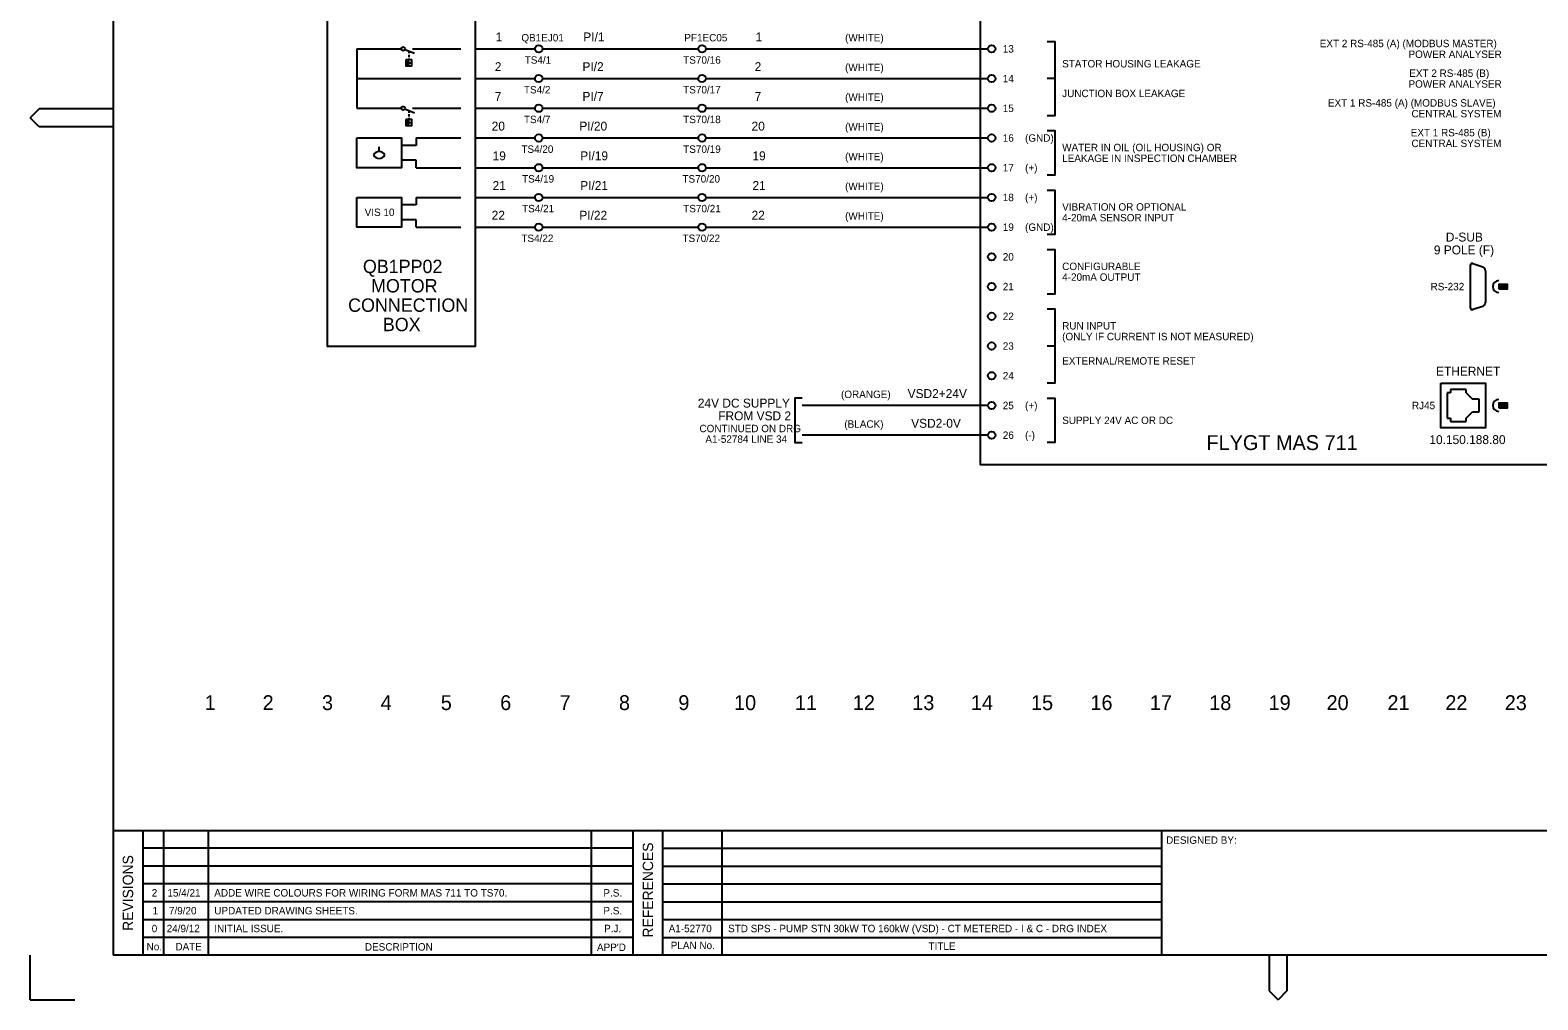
# Model space of a CAD drawing. Extents: x 0 to 841, y 0 to 594.
# Drawn here: x 0 to 508, y 0 to 326 of the extents above; entities that cross this region are included whole.
import ezdxf

# ---------------------------------------------------------------- set-up
doc = ezdxf.new("R2010")
doc.units = 0
for name, color, linetype in [('A1BORDER', 7, 'Continuous'), ('Level 1', 7, 'Continuous'), ('Level 10', 7, 'Continuous'), ('Level 5', 7, 'Continuous'), ('Level 6', 7, 'Continuous')]:
    doc.layers.add(name, color=color, linetype=linetype)

msp = doc.modelspace()

# ---------------------------------------------------------------- linework, layer by layer
at = {"layer": 'A1BORDER'}
for p, q in [((28, 581), (28, 15)), ((3, 299.76), (0, 296.76)), ((28, 299.76), (3, 299.76)), ((3, 293.76), (0, 296.76)), ((28, 293.76), (3, 293.76)), ((28, 57), (829, 57)), ((38, 15), (38, 57)), ((45, 15), (45, 57)), ((60, 15), (60, 57)), ((189, 15), (189, 57)), ((203, 15), (203, 57)), ((213, 15), (213, 57)), ((233, 15), (233, 57)), ((381, 15), (381, 57)), ((203, 51), (38, 51)), ((213, 51), (381, 51)), ((203, 45), (38, 45)), ((213, 45), (381, 45)), ((203, 39), (38, 39)), ((213, 39), (381, 39)), ((203, 33), (38, 33)), ((213, 33), (381, 33)), ((38, 27), (203, 27)), ((213, 27), (381, 27)), ((203, 21), (38, 21)), ((213, 21), (381, 21)), ((0, 0), (0, 15)), ((829, 15), (28, 15)), ((417.19, 15), (417.19, 3)), ((423.19, 15), (423.19, 3)), ((0, 0), (15, 0)), ((417.19, 3), (420.19, 0)), ((423.19, 3), (420.19, 0))]:
    msp.add_line(p, q, dxfattribs=at)
at = {"layer": 'Level 1'}
for p, q in [((110, 320), (125, 320)), ((110, 320), (110, 300)), ((128.75, 320), (130, 320)), ((130, 320), (145, 320)), ((227.5, 320), (322.5, 320)), ((126.2, 319.77), (129.38, 318.5)), ((127.5, 319.25), (127.5, 318.5)), ((127.5, 318), (127.5, 317.25)), ((127.5, 316.75), (127.5, 316.25)), ((127.64, 315.25), (128.15, 315.25)), ((110, 310), (145, 310)), ((227.5, 310), (322.5, 310)), ((345, 310), (342.5, 310)), ((110, 300), (125, 300)), ((126.2, 299.77), (129.38, 298.5)), ((128.75, 300), (130, 300)), ((130, 300), (145, 300)), ((227.5, 300), (322.5, 300)), ((127.5, 299.25), (127.5, 298.5)), ((127.5, 298), (127.5, 297.25)), ((127.5, 296.75), (127.5, 296.25)), ((127.64, 295.25), (128.15, 295.25)), ((130, 290), (145, 290)), ((130, 290), (130, 287.5)), ((227.5, 290), (322.5, 290)), ((130, 287.5), (125, 287.5)), ((130, 282.5), (125, 282.5)), ((130, 280), (130, 282.5)), ((130, 280), (145, 280)), ((227.5, 280), (322.5, 280)), ((130, 270), (145, 270)), ((130, 270), (130, 267.5)), ((227.5, 270), (322.5, 270)), ((130, 267.5), (125, 267.5)), ((130, 262.5), (125, 262.5)), ((130, 260), (130, 262.5)), ((130, 260), (145, 260)), ((227.5, 260), (322.5, 260)), ((485, 232.69), (485, 247.32)), ((485.72, 247.76), (489.17, 246.68)), ((490, 245.34), (490, 234.68)), ((494.5, 240.5), (497.5, 240.5)), ((494.5, 240.25), (497.5, 240.25)), ((494.5, 240), (497.5, 240)), ((494.5, 239.75), (497.5, 239.75)), ((494.5, 239.5), (497.5, 239.5)), ((489.17, 233.34), (485.72, 232.25)), ((345, 220), (342.5, 220)), ((477.14, 204.29), (477.14, 195.71)), ((478.21, 204.29), (477.14, 204.29)), ((483.57, 205.36), (478.21, 205.36)), ((478.21, 205.36), (478.21, 204.29)), ((483.57, 204.29), (483.57, 205.36)), ((483.57, 204.29), (485.71, 202.14)), ((322.5, 200), (260, 200)), ((487.86, 202.14), (485.71, 202.14)), ((487.86, 197.86), (487.86, 202.14)), ((494.5, 200.5), (497.5, 200.5)), ((494.5, 200.25), (497.5, 200.25)), ((494.5, 200), (497.5, 200)), ((494.5, 199.75), (497.5, 199.75)), ((494.5, 199.5), (497.5, 199.5)), ((477.14, 195.71), (478.21, 195.71)), ((478.21, 195.71), (478.21, 194.64)), ((478.21, 194.64), (483.57, 194.64)), ((483.57, 195.71), (485.71, 197.86)), ((483.57, 194.64), (483.57, 195.71)), ((485.71, 197.86), (487.86, 197.86)), ((322.5, 190), (260, 190))]:
    msp.add_line(p, q, dxfattribs=at)
for points in [[(150, 500), (100, 500), (100, 220), (150, 220)], [(320, 450), (520, 450), (520, 180), (320, 180)], [(126.5, 316.25), (126.5, 314.25), (128.5, 314.25), (128.5, 316.25)], [(126.5, 296.25), (126.5, 294.25), (128.5, 294.25), (128.5, 296.25)], [(110, 290), (125, 290), (125, 280), (110, 280)], [(110, 270), (125, 270), (125, 260), (110, 260)], [(475, 207.5), (490, 207.5), (490, 192.5), (475, 192.5)]]:
    msp.add_lwpolyline(points, close=True, dxfattribs=at)
for points in [[(342.5, 322.5), (345, 322.5), (345, 297.5), (342.5, 297.5)], [(342.5, 292.5), (345, 292.5), (345, 277.5), (342.5, 277.5)], [(342.5, 272.5), (345, 272.5), (345, 257.5), (342.5, 257.5)], [(342.5, 252.5), (345, 252.5), (345, 237.5), (342.5, 237.5)], [(342.5, 232.5), (345, 232.5), (345, 207.5), (342.5, 207.5)], [(260, 202.5), (257.5, 202.5), (257.5, 187.5), (260, 187.5)], [(342.5, 202.5), (345, 202.5), (345, 187.5), (342.5, 187.5)]]:
    msp.add_lwpolyline(points, dxfattribs=at)
for centre in [(125.63, 320), (125.63, 300)]:
    msp.add_circle(centre, 0.625, dxfattribs=at)
for centre, radius, start, end in [((127.56, 315.26), 0.699, 116.5651, 243.4349), ((126.93, 315.26), 0.699, 296.5651, 63.4349), ((127.56, 295.26), 0.699, 116.5651, 243.4349), ((126.93, 295.26), 0.699, 296.5651, 63.4349), ((485.5, 247.32), 0.5, 63.6594, 179.5468), ((488.5, 245.33), 1.5, 0.2965, 63.6295), ((488.5, 234.69), 1.5, 296.4323, 359.7035), ((485.5, 232.69), 0.5, 180.4532, 296.4699)]:
    msp.add_arc(centre, radius, start, end, dxfattribs=at)
at = {"layer": 'Level 10'}
msp.add_line((117.5, 285.45), (117.5, 287), dxfattribs=at)
for points in [[(494.5, 239.25), (497.5, 239.25), (497.5, 240.75), (494.5, 240.75)], [(494.5, 199.25), (497.5, 199.25), (497.5, 200.75), (494.5, 200.75)]]:
    msp.add_lwpolyline(points, close=True, dxfattribs=at)
for centre, radius, start, end in [((117.5, 283.36), 2.1, 26.5651, 153.435), ((117.5, 285.24), 2.1, 206.5651, 333.4349), ((494.5, 240), 2, 90, 270), ((494.5, 200), 2, 90, 270)]:
    msp.add_arc(centre, radius, start, end, dxfattribs=at)
at = {"layer": 'Level 5'}
for centre in [(171.25, 320), (226.25, 320), (323.75, 320), (171.25, 310), (226.25, 310), (323.75, 310), (171.25, 300), (226.25, 300), (323.75, 300), (171.25, 290), (226.25, 290), (323.75, 290), (171.25, 280), (226.25, 280), (323.75, 280), (171.25, 270), (226.25, 270), (323.75, 270), (171.25, 260), (226.25, 260), (323.75, 260), (323.75, 250), (323.75, 240), (323.75, 230), (323.75, 220), (323.75, 210), (323.75, 200), (323.75, 190)]:
    msp.add_circle(centre, 1.25, dxfattribs=at)
at = {"layer": 'Level 6'}
for p, q in [((150, 320), (170, 320)), ((172.5, 320), (225, 320)), ((150, 310), (170, 310)), ((172.5, 310), (225, 310)), ((150, 300), (170, 300)), ((172.5, 300), (225, 300)), ((150, 290), (170, 290)), ((172.5, 290), (225, 290)), ((150, 280), (170, 280)), ((172.5, 280), (225, 280)), ((150, 270), (170, 270)), ((172.5, 270), (225, 270)), ((150, 260), (170, 260)), ((172.5, 260), (225, 260))]:
    msp.add_line(p, q, dxfattribs=at)

# ---------------------------------------------------------------- texts
at = {"layer": 'A1BORDER'}
for s, p in [('REFERENCES', (209.76, 20.96)), ('REVISIONS', (34.68, 23.2))]:
    msp.add_text(s, height=3.5, rotation=90, dxfattribs=at).set_placement(p)
for s, p in [('DESIGNED BY:', (382.5, 52.5)), ('No.', (39.21, 16.65)), ('DATE', (48.92, 16.65)), ('DESCRIPTION', (112.71, 16.57)), ("APP'D", (190.85, 16.44)), ('PLAN No.', (215.69, 17.06)), ('TITLE', (302.5, 16.81))]:
    msp.add_text(s, height=2.5, dxfattribs=at).set_placement(p)
at = {"layer": 'Level 1'}
for s, height, p in [('QB1EJ01', 2.5, (165.4, 322.5)), ('PF1EC05', 2.5, (220.27, 322.5)), ('13', 2.5, (327.5, 318.75)), ('EXT 2 RS-485 (A) (MODBUS MASTER)', 2.5, (434.23, 320.56)), ('TS4/1', 2.5, (166.52, 315)), ('TS70/16', 2.5, (219.9, 315)), ('STATOR HOUSING LEAKAGE', 2.5, (347.5, 313.75)), ('POWER ANALYSER', 2.5, (464.11, 316.94)), ('14', 2.5, (327.5, 308.75)), ('EXT 2 RS-485 (B)', 2.5, (464.36, 310.56)), ('TS4/2', 2.5, (166.27, 305)), ('TS70/17', 2.5, (219.9, 305)), ('JUNCTION BOX LEAKAGE', 2.5, (347.5, 303.75)), ('POWER ANALYSER', 2.5, (464.11, 306.94)), ('15', 2.5, (327.5, 298.75)), ('EXT 1 RS-485 (A) (MODBUS SLAVE)', 2.5, (436.97, 300.56)), ('TS4/7', 2.5, (166.27, 295)), ('TS70/18', 2.5, (219.9, 295)), ('CENTRAL SYSTEM', 2.5, (465.11, 296.94)), ('16', 2.5, (327.5, 288.75)), ('(GND)', 2.5, (335, 288.75)), ('EXT 1 RS-485 (B)', 2.5, (464.86, 290.56)), ('CENTRAL SYSTEM', 2.5, (465.11, 286.94)), ('TS4/20', 2.5, (165.4, 285)), ('TS70/19', 2.5, (219.9, 285)), ('WATER IN OIL (OIL HOUSING) OR', 2.5, (347.5, 285.56)), ('LEAKAGE IN INSPECTION CHAMBER', 2.5, (347.5, 281.94)), ('17', 2.5, (327.5, 278.75)), ('(+)', 2.5, (335, 278.75)), ('TS4/19', 2.5, (165.65, 275)), ('TS70/20', 2.5, (219.65, 275)), ('18', 2.5, (327.5, 268.75)), ('(+)', 2.5, (335, 268.75)), ('VIS 10', 2.5, (112.64, 263.75)), ('TS4/21', 2.5, (165.65, 265)), ('TS70/21', 2.5, (219.9, 265)), ('VIBRATION OR OPTIONAL', 2.5, (347.5, 265.56)), ('4-20mA SENSOR INPUT', 2.5, (347.5, 261.94)), ('19', 2.5, (327.5, 258.75)), ('(GND)', 2.5, (335, 258.75)), ('TS4/22', 2.5, (165.4, 255)), ('TS70/22', 2.5, (219.65, 255)), ('20', 2.5, (327.5, 248.75)), ('4-20mA OUTPUT', 2.5, (347.5, 241.94)), ('CONFIGURABLE', 2.5, (347.5, 245.56)), ('21', 2.5, (327.5, 238.75)), ('RS-232', 2.5, (471.54, 238.75)), ('22', 2.5, (327.5, 228.75)), ('(ONLY IF CURRENT IS NOT MEASURED)', 2.5, (347.5, 221.94)), ('RUN INPUT', 2.5, (347.5, 225.56)), ('23', 2.5, (327.5, 218.75)), ('EXTERNAL/REMOTE RESET', 2.5, (347.5, 213.75)), ('24', 2.5, (327.5, 208.75)), ('24V DC SUPPLY', 3, (224.82, 199.29)), ('FROM VSD 2', 3, (231.69, 195)), ('25', 2.5, (327.5, 198.75)), ('(+)', 2.5, (335, 198.75)), ('RJ45', 2.5, (465.28, 198.75)), ('CONTINUED ON DRG', 2.5, (225.37, 191)), ('SUPPLY 24V AC OR DC', 2.5, (347.5, 193.75)), ('A1-52784 LINE 34', 2.5, (227.36, 187.43)), ('26', 2.5, (327.5, 188.75)), ('(-)', 2.5, (335, 188.75)), ('1', 5, (58.76, 97.5)), ('2', 5, (78.26, 97.5)), ('3', 5, (98.26, 97.5)), ('4', 5, (118.01, 97.5)), ('5', 5, (138.26, 97.5)), ('6', 5, (158.26, 97.5)), ('7', 5, (178.26, 97.5)), ('8', 5, (198.26, 97.5)), ('9', 5, (218.26, 97.5)), ('10', 5, (237.01, 97.5)), ('11', 5, (257.51, 97.5)), ('12', 5, (277.01, 97.5)), ('13', 5, (297.01, 97.5)), ('14', 5, (316.77, 97.5)), ('15', 5, (337.01, 97.5)), ('16', 5, (357.01, 97.5)), ('17', 5, (377.01, 97.5)), ('18', 5, (397.01, 97.5)), ('19', 5, (417.01, 97.5)), ('20', 5, (436.52, 97.5)), ('21', 5, (457.01, 97.5)), ('22', 5, (476.52, 97.5)), ('23', 5, (496.52, 97.5)), ('2', 2.5, (40.94, 34.75)), ('15/4/21', 2.5, (46.22, 34.75)), ('ADDE WIRE COLOURS FOR WIRING FORM MAS 711 TO TS70.', 2.5, (62, 34.75)), ('P.S.', 2.5, (193.02, 34.75)), ('1', 2.5, (41.19, 28.75)), ('7/9/20', 2.5, (46.72, 28.75)), ('UPDATED DRAWING SHEETS.', 2.5, (62, 28.75)), ('P.S.', 2.5, (193.02, 28.75)), ('0', 2.5, (40.94, 22.75)), ('24/9/12', 2.5, (45.97, 22.75)), ('INITIAL ISSUE.', 2.5, (62, 22.75)), ('P.J.', 2.5, (193.26, 22.75)), ('A1-52770', 2.5, (215, 22.75)), ('STD SPS - PUMP STN 30kW TO 160kW (VSD) - CT METERED - I & C - DRG INDEX', 2.5, (235, 22.75))]:
    msp.add_text(s, height=height, dxfattribs=at).set_placement(p)
for s, height, p in [('QB1PP02', 4.5, (112.05, 244.54)), ('MOTOR', 4.5, (114.79, 238.03)), ('CONNECTION', 4.5, (107.07, 231.51)), ('BOX', 4.5, (118.77, 225)), ('FLYGT MAS 711', 5, (396.09, 185))]:
    msp.add_text(s, height=height, rotation=360, dxfattribs=at).set_placement(p)
at = {"layer": 'Level 5'}
for s, height, p in [('1', 3, (156.75, 322.5)), ('PI/1', 3, (186.26, 322.5)), ('1', 3, (244.25, 322.5)), ('(WHITE)', 2.5, (274.4, 322.5)), ('2', 3, (156.45, 312.5)), ('PI/2', 3, (185.97, 312.5)), ('2', 3, (243.95, 312.5)), ('(WHITE)', 2.5, (274.4, 312.5)), ('7', 3, (156.45, 302.5)), ('PI/7', 3, (185.97, 302.5)), ('7', 3, (243.95, 302.5)), ('(WHITE)', 2.5, (274.4, 302.5)), ('20', 3, (155.41, 292.5)), ('PI/20', 3, (184.92, 292.5)), ('20', 3, (242.91, 292.5)), ('(WHITE)', 2.5, (274.4, 292.5)), ('19', 3, (155.71, 282.5)), ('PI/19', 3, (185.22, 282.5)), ('19', 3, (243.21, 282.5)), ('(WHITE)', 2.5, (274.4, 282.5)), ('21', 3, (155.71, 272.5)), ('PI/21', 3, (185.22, 272.5)), ('21', 3, (243.21, 272.5)), ('(WHITE)', 2.5, (274.4, 272.5)), ('22', 3, (155.41, 262.5)), ('PI/22', 3, (184.92, 262.5)), ('22', 3, (242.91, 262.5)), ('(WHITE)', 2.5, (274.4, 262.5)), ('9 POLE (F)', 3, (472.64, 250.83)), ('D-SUB', 3, (476.67, 255.17)), ('ETHERNET', 3, (473.39, 210)), ('(ORANGE)', 2.5, (273.03, 202.5)), ('VSD2+24V', 3, (295.46, 202.5)), ('(BLACK)', 2.5, (274.15, 192.5)), ('VSD2-0V', 3, (296.66, 192.5)), ('10.150.188.80', 3, (471.14, 187))]:
    msp.add_text(s, height=height, dxfattribs=at).set_placement(p)

doc.saveas('drawing.dxf')
